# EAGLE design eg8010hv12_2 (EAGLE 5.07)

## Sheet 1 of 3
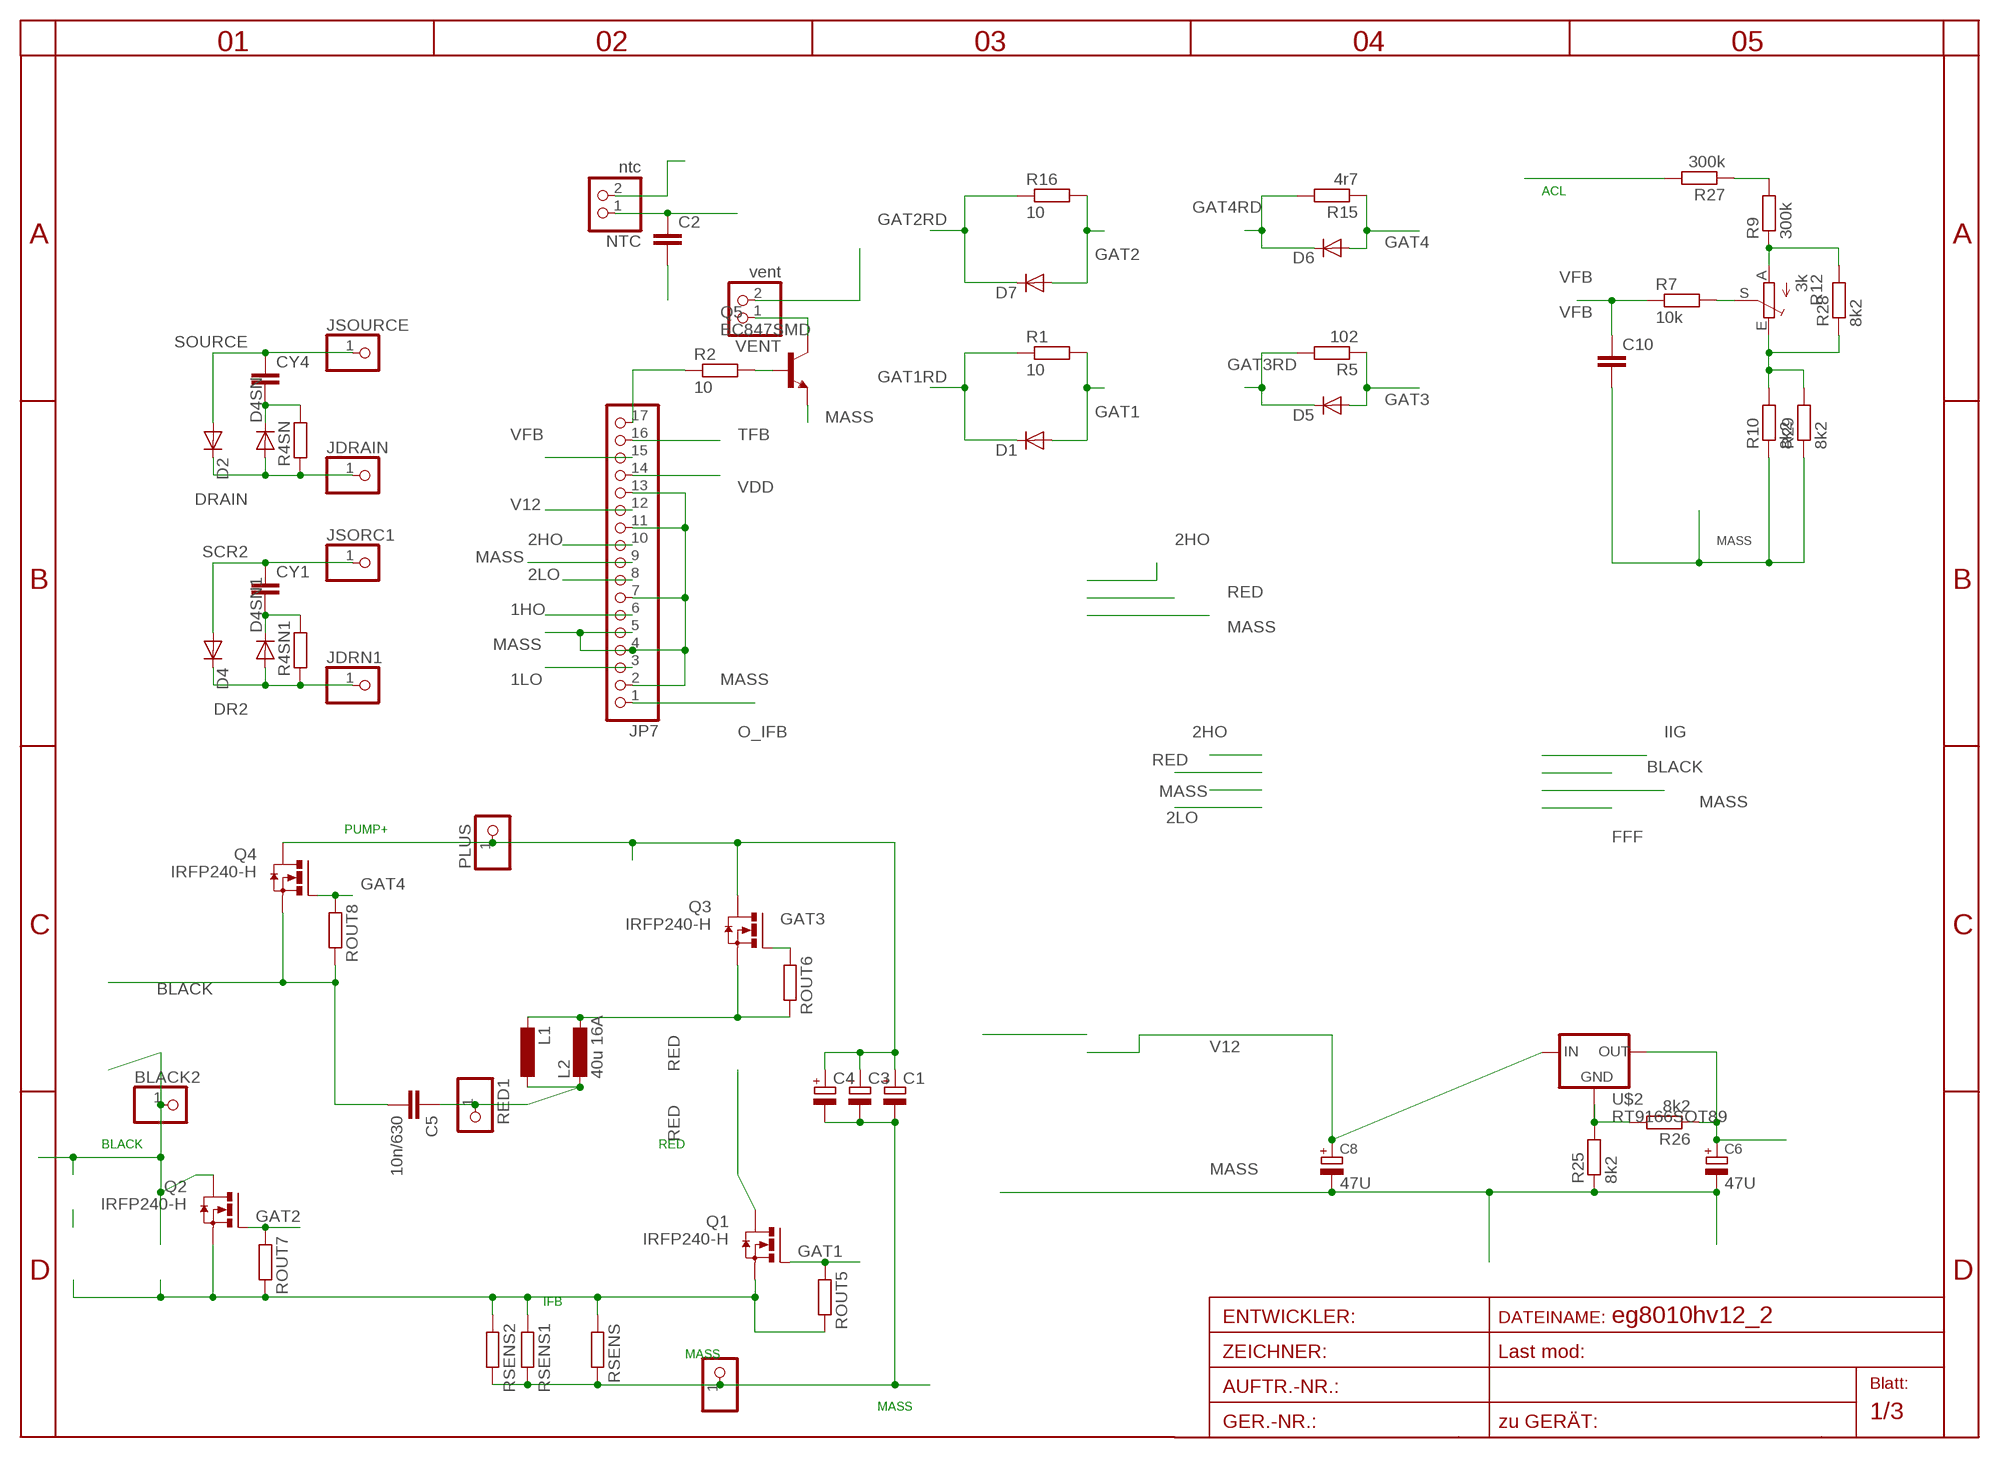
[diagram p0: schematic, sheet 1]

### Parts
BLACK2  PINHD-1X12MM3  [1X2MM3]
C1  CPOL-EUE5-13  [E5-13]
C2  C-EUC1206  [C1206]
C3  CPOL-EUE5-13  [E5-13]
C4  CPOL-EUE5-13  [E5-13]
C5  10n/630  C-EU275-173X316  [C275-173X316]
C6  47U  CPOL-EUSMCA  [SMC_A]
C8  47U  CPOL-EUSMCA  [SMC_A]
C10  C-EUC0805  [C0805]
CY1  CXXC10B5  [XC10B5]
CY4  CXXC10B5  [XC10B5]
D1  DIODE-SMA-DO214  [SMA-DO214AC]
D2  DIODE-SMC  [SMC]
D4  DIODE-SMC  [SMC]
D4SN  DIODE-P1-10  [P1-10]
D4SN1  DIODE-P1-10  [P1-10]
D5  DIODE-MINIMELF  [MINIMELF]
D6  DIODE-SMA-DO214  [SMA-DO214AC]
D7  DIODE-SMA-DO214  [SMA-DO214AC]
JDRAIN  PINHD-1X11MM0  [1X1MM0]
JDRN1  PINHD-1X11MM0  [1X1MM0]
JP7  PINHD-1X17  [1X17]
JSORC1  PINHD-1X11MM0  [1X1MM0]
JSOURCE  PINHD-1X11MM0  [1X1MM0]
L1  L-EU4.13  [0204/13]
L2  40u 16A  L-EURNG  [RING]
MINUS  PINHD-1X12MM3  [1X2MM3]
NTC  ntc  PINHD-1X2STR  [1X02]
PLUS  PINHD-1X12MM3  [1X2MM3]
Q1  IRFP240-H  [TO247BH]
Q2  IRFP240-H  [TO247BH]
Q3  IRFP240-H  [TO247BH]
Q4  IRFP240-H  [TO247BH]
Q5  BC847SMD  [SOT23]
R1  10  R-EU_R1206  [R1206]
R2  10  R-EU_R0805  [R0805]
R4SN  R-EU_0207/10  [0207/10]
R4SN1  R-EU_0207/10  [0207/10]
R5  102  R-EU_R1206  [R1206]
R7  10k  R-EU_R0805  [R0805]
R9  300k  R-EU_R1206  [R1206]
R10  8k2  R-EU_R0805  [R0805]
R12  3k  TRIM_EU-B64Y  [B64Y]
R15  4r7  R-EU_R1206  [R1206]
R16  10  R-EU_R1206  [R1206]
R25  8k2  R-EU_R0805  [R0805]
R26  8k2  R-EU_R0805  [R0805]
R27  300k  R-EU_R1206  [R1206]
R28  8k2  R-EU_R1206  [R1206]
R29  8k2  R-EU_R0805  [R0805]
RED1  PINHD-1X12MM3  [1X2MM3]
ROUT5  R-EU_R1206  [R1206]
ROUT6  R-EU_R1206  [R1206]
ROUT7  R-EU_R1206  [R1206]
ROUT8  R-EU_R1206  [R1206]
RSENS  R-EU_0204/7  [0204/7]
RSENS1  R-EU_0204/7  [0204/7]
RSENS2  R-EU_0922V  [0922V]
U$2  RT9166SOT89  [SOT89R]
VENT  vent  PINHD-1X2STR  [1X02]

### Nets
1HO: JP7.6 ; also sheet 3
1LO: JP7.3 ; also sheet 3
2HO: JP7.10 ; also sheet 3
2LO: JP7.8 ; also sheet 3
ACL: C5.1 L1.1 L2.2 R27.2 RED1.1
BLACK: BLACK2.1 C5.2 Q2.D Q4.S ROUT8.2 ; also sheet 3
DR2: D4.C D4SN1.A JDRN1.1 R4SN1.1
DRAIN: D2.C D4SN.A JDRAIN.1 R4SN.1
GAT1: D1.A Q1.G R1.2 ROUT5.1
GAT1RD: D1.K(C) R1.1 ; also sheet 3
GAT2: D7.A Q2.G R16.2 ROUT7.1
GAT2RD: D7.K(C) R16.1 ; also sheet 3
GAT3: D5.A Q3.G R5.1 ROUT6.1
GAT3RD: D5.C R5.2 ; also sheet 3
GAT4: D6.A Q4.G R15.1 ROUT8.1
GAT4RD: D6.K(C) R15.2 ; also sheet 3
IFB: Q1.S Q2.S ROUT5.2 ROUT7.2 RSENS1.1 RSENS2.1 RSENS.1 ; also sheet 3
MASS: C1.- C2.2 C3.- C4.- C6.- C8.- C10.2 JP7.2 JP7.4 JP7.5 JP7.7 JP7.9 JP7.11 JP7.13 MINUS.1 Q5.2(E) R10.1 R25.1 R29.1 RSENS1.2 RSENS2.2 RSENS.2 ; also sheet 2,3
N$1: Q5.3(C) VENT.1
N$2: Q5.1(B) R2.2
N$3: JP7.17 R2.1
N$17: R25.2 R26.2 U$2.3(GND) U$2.4(GND1)
N$23: R9.2 R27.1
N$29: R10.2 R12.E R28.1 R29.2
N$30: R9.1 R12.A R28.2
N$31: R7.2 R12.S
O_IFB: JP7.1 ; also sheet 3
PUMP+: C1.+ C3.+ C4.+ PLUS.1 Q3.D Q4.D ; also sheet 2
RED: L1.2 L2.1 Q1.D Q3.S ROUT6.2 ; also sheet 3
SCR2: CY1.1 D4.A JSORC1.1
SNUB1: CY1.2 D4SN1.C R4SN1.2
SNUB2: CY4.2 D4SN.C R4SN.2
SOURCE: CY4.1 D2.A JSOURCE.1
TFB: C2.1 JP7.16 NTC.1
V12: C8.+ JP7.12 U$2.1(IN) ; also sheet 2,3
VDD: C6.+ JP7.14 NTC.2 R26.1 U$2.2(OUT) VENT.2
VFB: C10.1 JP7.15 R7.1

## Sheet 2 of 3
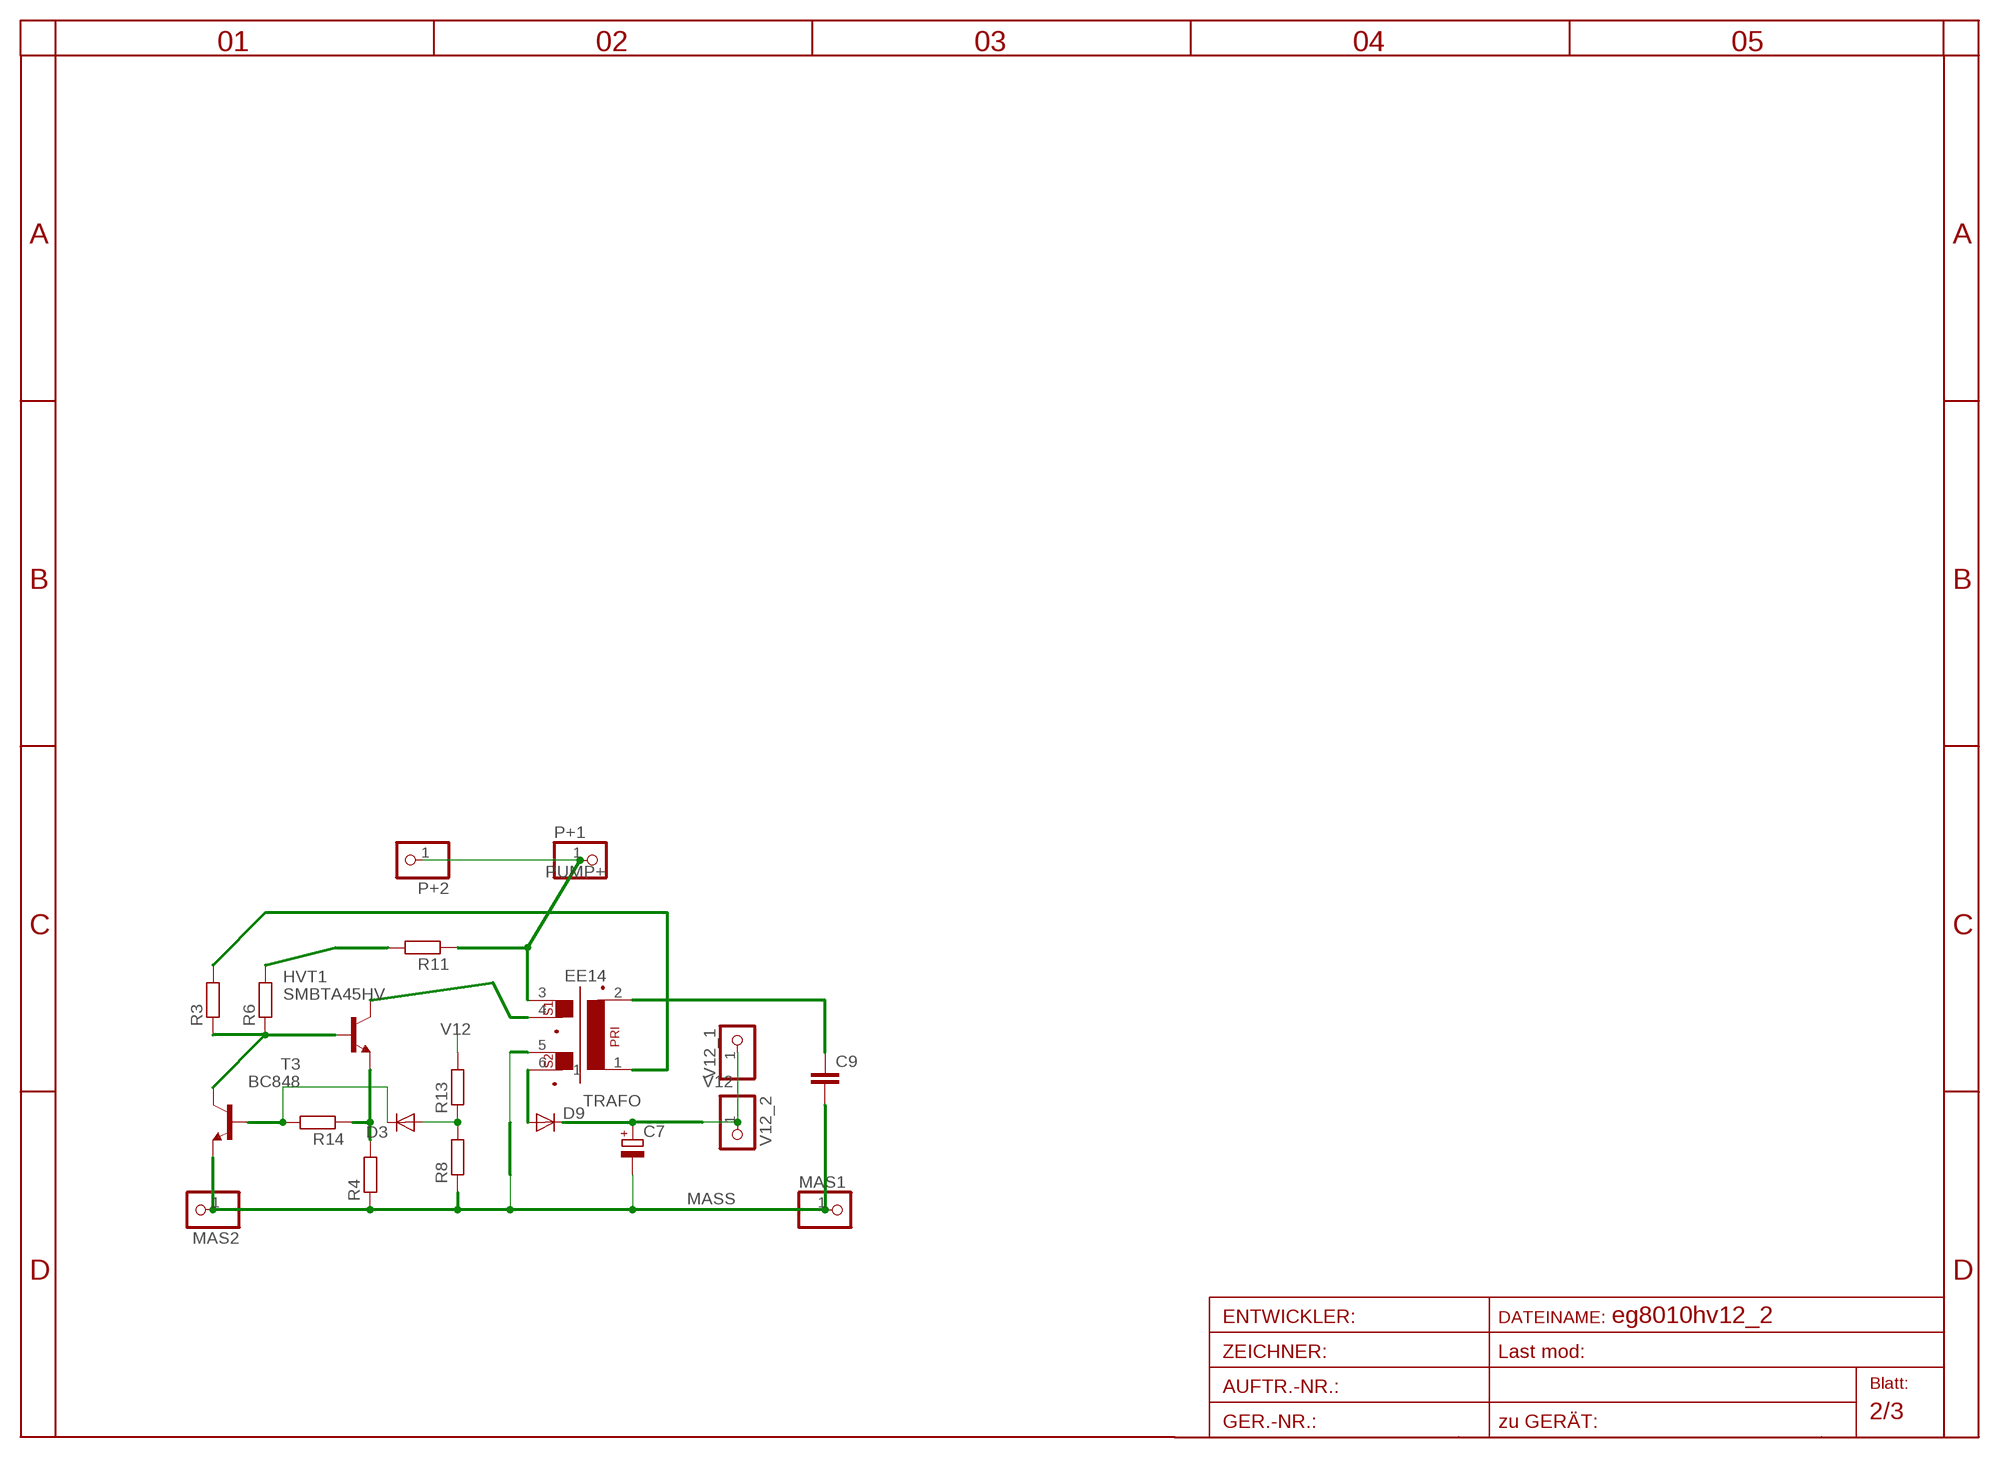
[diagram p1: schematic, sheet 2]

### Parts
C7  CPOL-EUSMCA  [SMC_A]
C9  C-EUC0805  [C0805]
D3  DIODE-MINIMELF  [MINIMELF]
D9  DIODE-SMA-DO214  [SMA-DO214AC]
HVT1  SMBTA45HV  [SOT23HV]
MAS1  PINHD-1X11X0.4  [1X01]
MAS2  PINHD-1X11X0.4  [1X01]
P+1  PINHD-1X11X0.4  [1X01]
P+2  PINHD-1X11X0.4  [1X01]
R3  R-EU_R0805  [R0805]
R4  R-EU_R0805  [R0805]
R6  R-EU_R1206  [R1206]
R8  R-EU_R0805  [R0805]
R11  R-EU_R1206  [R1206]
R13  R-EU_R0805  [R0805]
R14  R-EU_R0805  [R0805]
T3  BC848  [SOT23]
TRAFO  EE14  [EE14]
V12_1  PINHD-1X11X0.4  [1X01]
V12_2  PINHD-1X11X0.4  [1X01]

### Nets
A: D9.A TRAFO.6
B1C2: HVT1.1(B) R3.1 R6.1 T3.C
BT1: D3.C R14.2 T3.B
C1: HVT1.3(C) TRAFO.4
EB: HVT1.2(E) R4.2 R14.1
MASS: C7.- C9.2 MAS1.1 MAS2.1 R4.1 R8.1 T3.E TRAFO.5 ; also sheet 1,3
N$6: R3.2 TRAFO.1
N$7: C9.1 TRAFO.2
N$8: R6.2 R11.2
N$10: D3.A R8.2 R13.1
PUMP+: P+1.1 P+2.1 R11.1 TRAFO.3 ; also sheet 1
V12: C7.+ D9.K(C) R13.2 V12_1.1 V12_2.1 ; also sheet 1,3

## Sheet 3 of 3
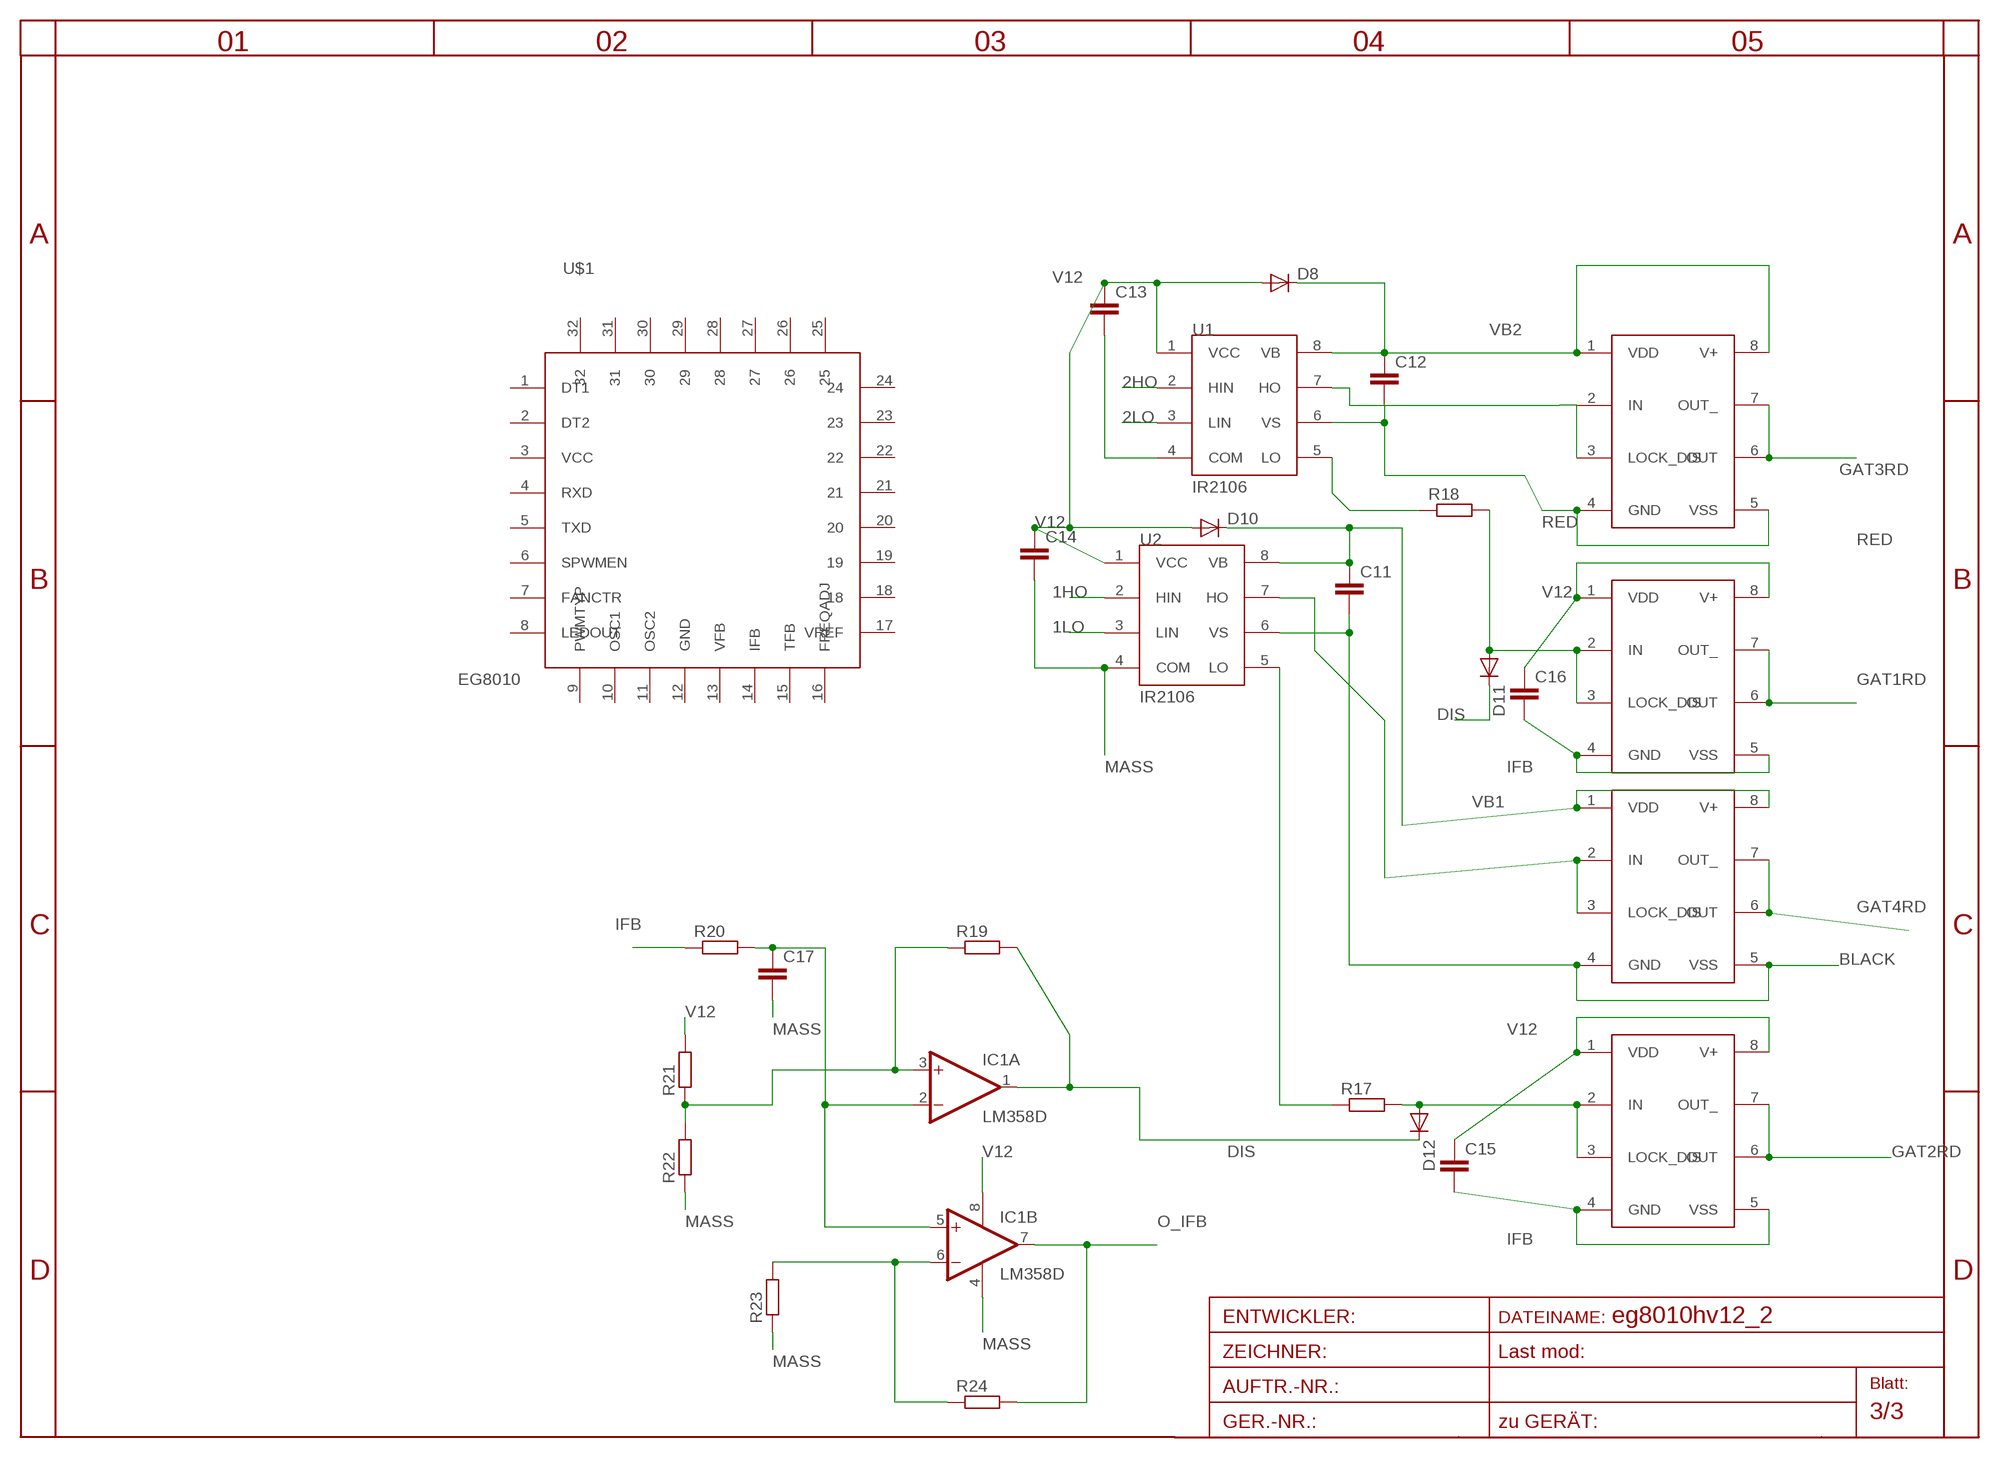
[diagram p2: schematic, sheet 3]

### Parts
1HDRV  TC4432X  [SO-08]
1LODRV  TC4432X  [SO-08]
2HDRV  TC4432X  [SO-08]
2LODRV  TC4432X  [SO-08]
C11  C-EUC1206  [C1206]
C12  C-EUC1206  [C1206]
C13  C-EUC1206  [C1206]
C14  C-EUC1206  [C1206]
C15  C-EUC1206  [C1206]
C16  C-EUC1206  [C1206]
C17  C-EUC1206  [C1206]
D8  DIODE-SMA-DO214  [SMA-DO214AC]
D10  DIODE-SMA-DO214  [SMA-DO214AC]
D11  DIODE-SOT23  [SOT23]
D12  DIODE-SOT23  [SOT23]
IC1  LM358D  [SO08]
R17  R-EU_0617/17  [0617/17]
R18  R-EU_0204/7  [0204/7]
R19  R-EU_R1206  [R1206]
R20  R-EU_R0805  [R0805]
R21  R-EU_R0805  [R0805]
R22  R-EU_R0805  [R0805]
R23  R-EU_R0805  [R0805]
R24  R-EU_R0805  [R0805]
U1  IR2106  [SO8-2]
U2  IR2106  [SO8-2]
U$1  EG8010  [EG8010-32]

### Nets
1HO: U2.2(HIN) ; also sheet 1
1LO: U2.3(LIN) ; also sheet 1
2HO: U1.2(HIN) ; also sheet 1
2LO: U1.3(LIN) ; also sheet 1
BLACK: 1HDRV.4(GND) 1HDRV.5(VSS) C11.2 U2.6(VS) ; also sheet 1
DIS: D11.3(C) D12.3(C) IC1.1(A:OUT) R19.2
GAT1RD: 2LODRV.6(OUT) 2LODRV.7(OUT_) ; also sheet 1
GAT2RD: 1LODRV.6(OUT) 1LODRV.7(OUT_) ; also sheet 1
GAT3RD: 2HDRV.6(OUT) 2HDRV.7(OUT_) ; also sheet 1
GAT4RD: 1HDRV.6(OUT) 1HDRV.7(OUT_) ; also sheet 1
IFB: 1LODRV.4(GND) 1LODRV.5(VSS) 2LODRV.4(GND) 2LODRV.5(VSS) C15.2 C16.2 R20.1 ; also sheet 1
MASS: C13.2 C14.2 C17.2 IC1.4(P:V-) R22.1 R23.1 U1.4(COM) U2.4(COM) ; also sheet 1,2
N$4: R18.1 U1.5(LO)
N$5: 1LODRV.2(IN) 1LODRV.3(LOCK_DIS) D12.1(A) R17.2
N$9: IC1.3(A:+IN) R19.1 R21.1 R22.2
N$11: R17.1 U2.5(LO)
N$12: 2HDRV.2(IN) 2HDRV.3(LOCK_DIS) U1.7(HO)
N$13: 1HDRV.2(IN) 1HDRV.3(LOCK_DIS) U2.7(HO)
N$15: C17.1 IC1.2(A:-IN) IC1.5(B:+IN) R20.2
N$16: 2LODRV.2(IN) 2LODRV.3(LOCK_DIS) D11.1(A) R18.2
N$18: IC1.6(B:-IN) R23.2 R24.1
O_IFB: IC1.7(B:OUT) R24.2 ; also sheet 1
RED: 2HDRV.4(GND) 2HDRV.5(VSS) C12.2 U1.6(VS) ; also sheet 1
V12: 1LODRV.1(VDD) 1LODRV.8(V+) 2LODRV.1(VDD) 2LODRV.8(V+) C13.1 C14.1 C15.1 C16.1 D8.A D10.A IC1.8(P:V+) R21.2 U1.1(VCC) U2.1(VCC) ; also sheet 1,2
VB1: 1HDRV.1(VDD) 1HDRV.8(V+) C11.1 D10.K(C) U2.8(VB)
VB2: 2HDRV.1(VDD) 2HDRV.8(V+) C12.1 D8.K(C) U1.8(VB)
Unconnected: U$1.1(DT1) U$1.2(DT2) U$1.4(RXD) U$1.5(TXD) U$1.6(SPWMEN) U$1.8(LEDOUT) U$1.9(PWMTYP) U$1.10(OSC1) U$1.11(OSC2) U$1.12(GND) U$1.13(VFB) U$1.14(IFB) U$1.15(TFB) U$1.16(FREQADJ) U$1.17(VREF) U$1.18 U$1.19 U$1.20 U$1.21 U$1.22 U$1.23 U$1.24 U$1.26 U$1.27 U$1.29 U$1.30 U$1.31 U$1.32

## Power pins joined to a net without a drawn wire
25: U$1.25
28: U$1.28
FANCTR: U$1.7(FANCTR)
VCC: U$1.3(VCC)

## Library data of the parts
1HDRV 1LODRV 2HDRV 2LODRV = microchip:TC4432
BLACK2 JDRAIN JDRN1 JSORC1 JSOURCE MAS1 MAS2 MINUS P+1 P+2 PLUS RED1 V12_1 V12_2 = pinhead:PINHD-1X1: PIN HEADER
C1 C3 C4 C6-C8 = rcl:CPOL-EU: POLARIZED CAPACITOR, European symbol
C2 C5 C9-C17 = rcl:C-EU: CAPACITOR, European symbol
CY1 CY4 = rcl:CX: X CAPACITOR
D1-D4 D4SN D4SN1 D5-D12 = diode:DIODE-: DIODE
HVT1 = transistor-npn:SMBTA45
IC1 = linear:LM358: OP AMP also LM158; LM258; LM2904 Source: http://cache.national.com/ds/LM/LM158.pdf
JP7 = pinhead:PINHD-1X17: PIN HEADER
L1 L2 = rcl:L-EU: INDUCTOR, European symbol
NTC VENT = pinhead:PINHD-1X2: PIN HEADER
Q1-Q4 = transistor-power:IRFP240: HEXFET Power MosFet Source: http://www.irf.com/
Q5 = transistor-npn:BC847*: NPN Transistor
R1-R4 R4SN R4SN1 R5 R6 R8 R11 R13-R16 R18-R24 ROUT5-ROUT8 RSENS RSENS1 RSENS2 = rcl:R-EU_: RESISTOR, European symbol
R7 R9 R10 R17 R25-R29 = rcl-2:R-EU_: RESISTOR, European symbol
R12 = pot:TRIM_EU-: POTENTIOMETER
T3 = transistor:BC848: NPN TRANSISTOR
TRAFO = trafo:EE14
U1 U2 = irf-2:IR2106
U$1 = texas:EG8010
U$2 = v-reg:RT9166

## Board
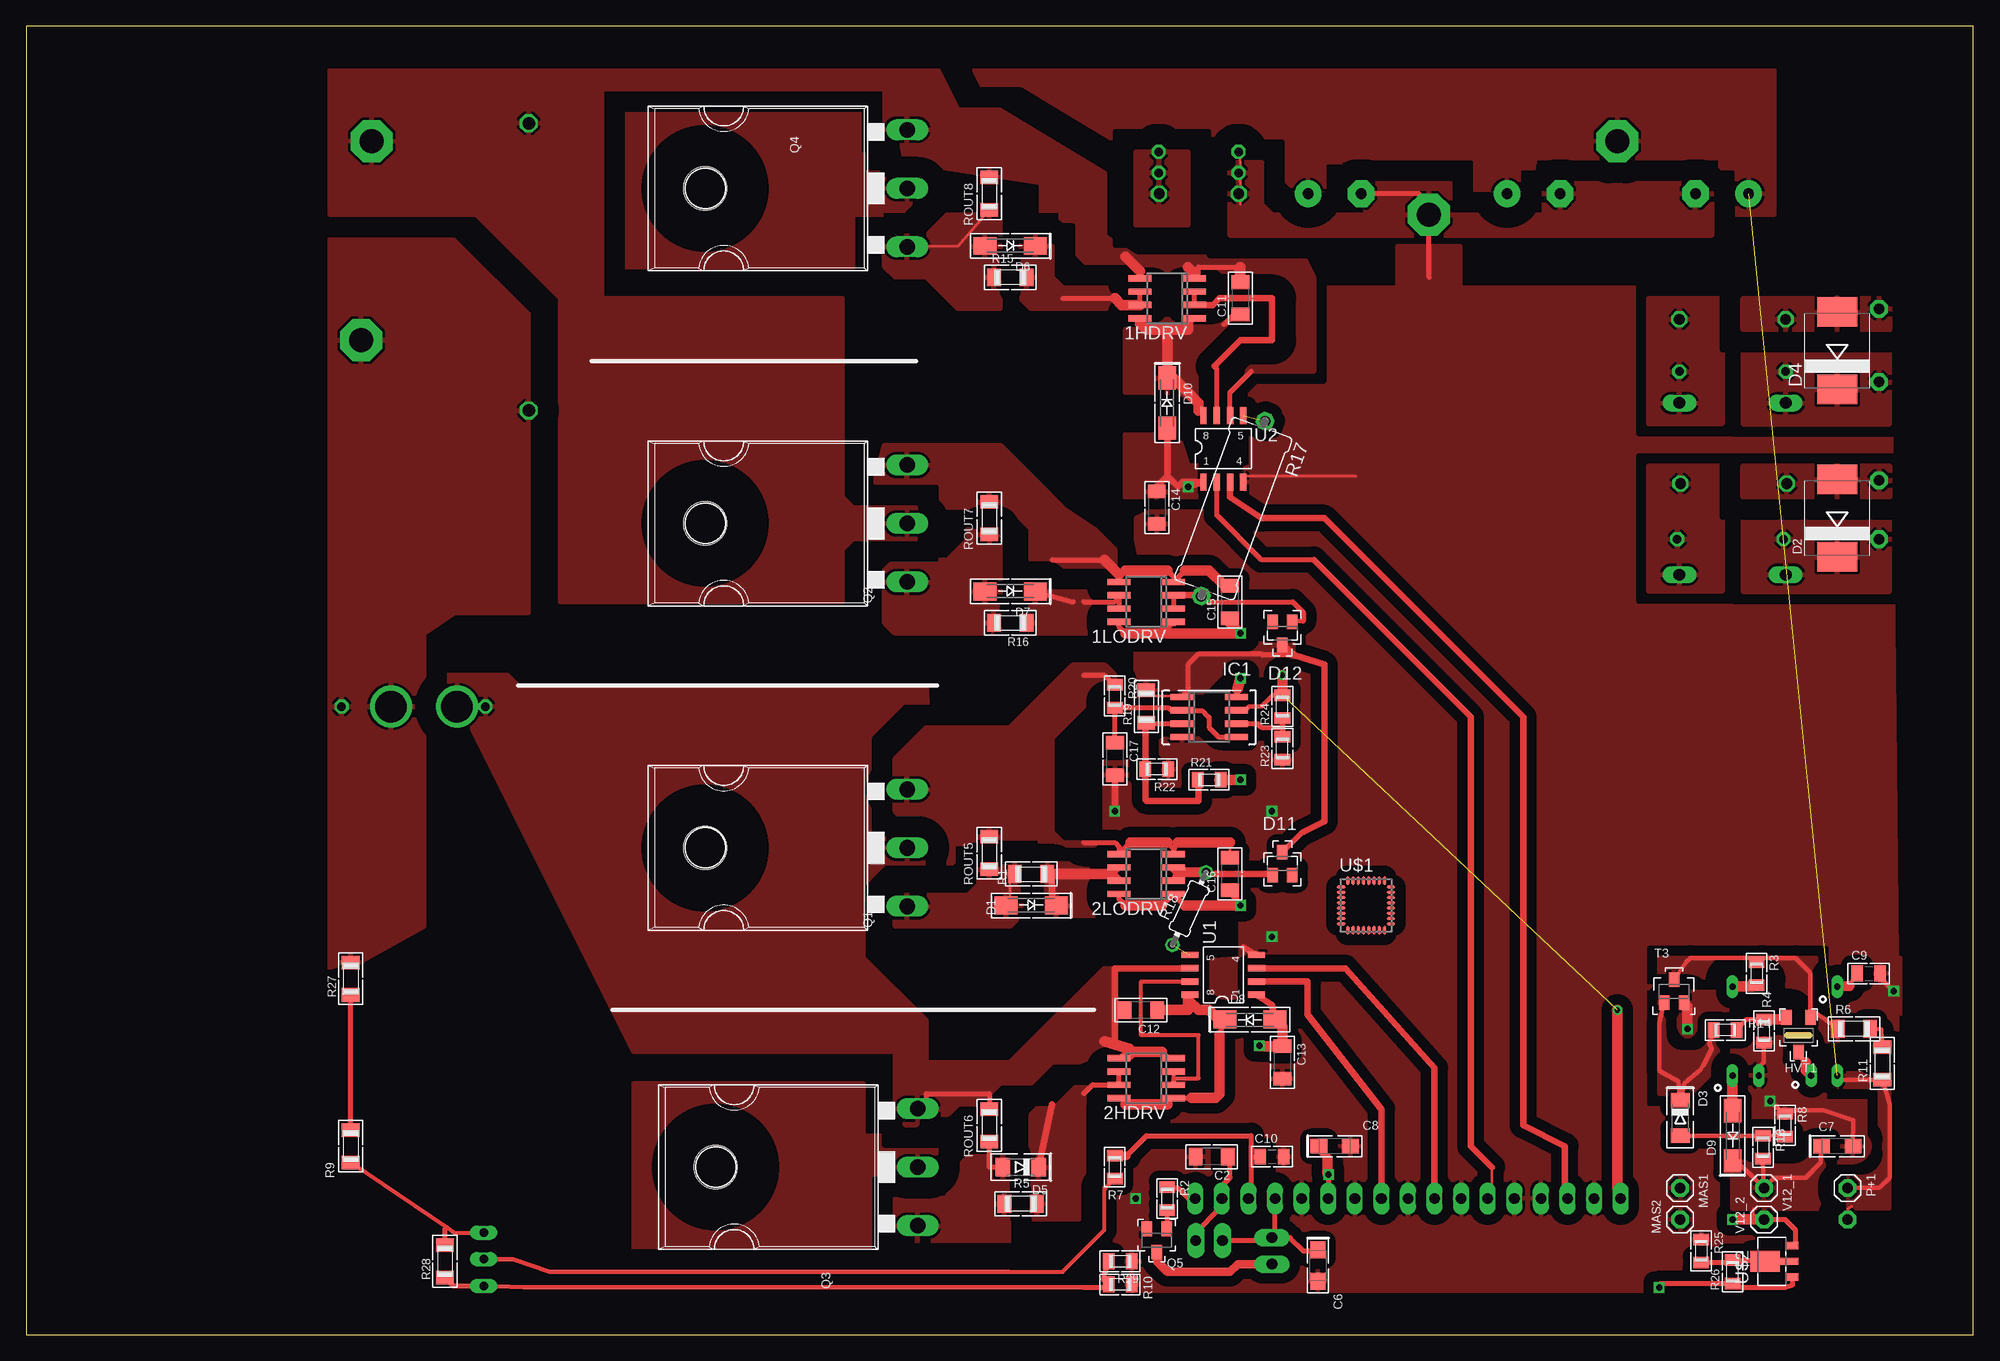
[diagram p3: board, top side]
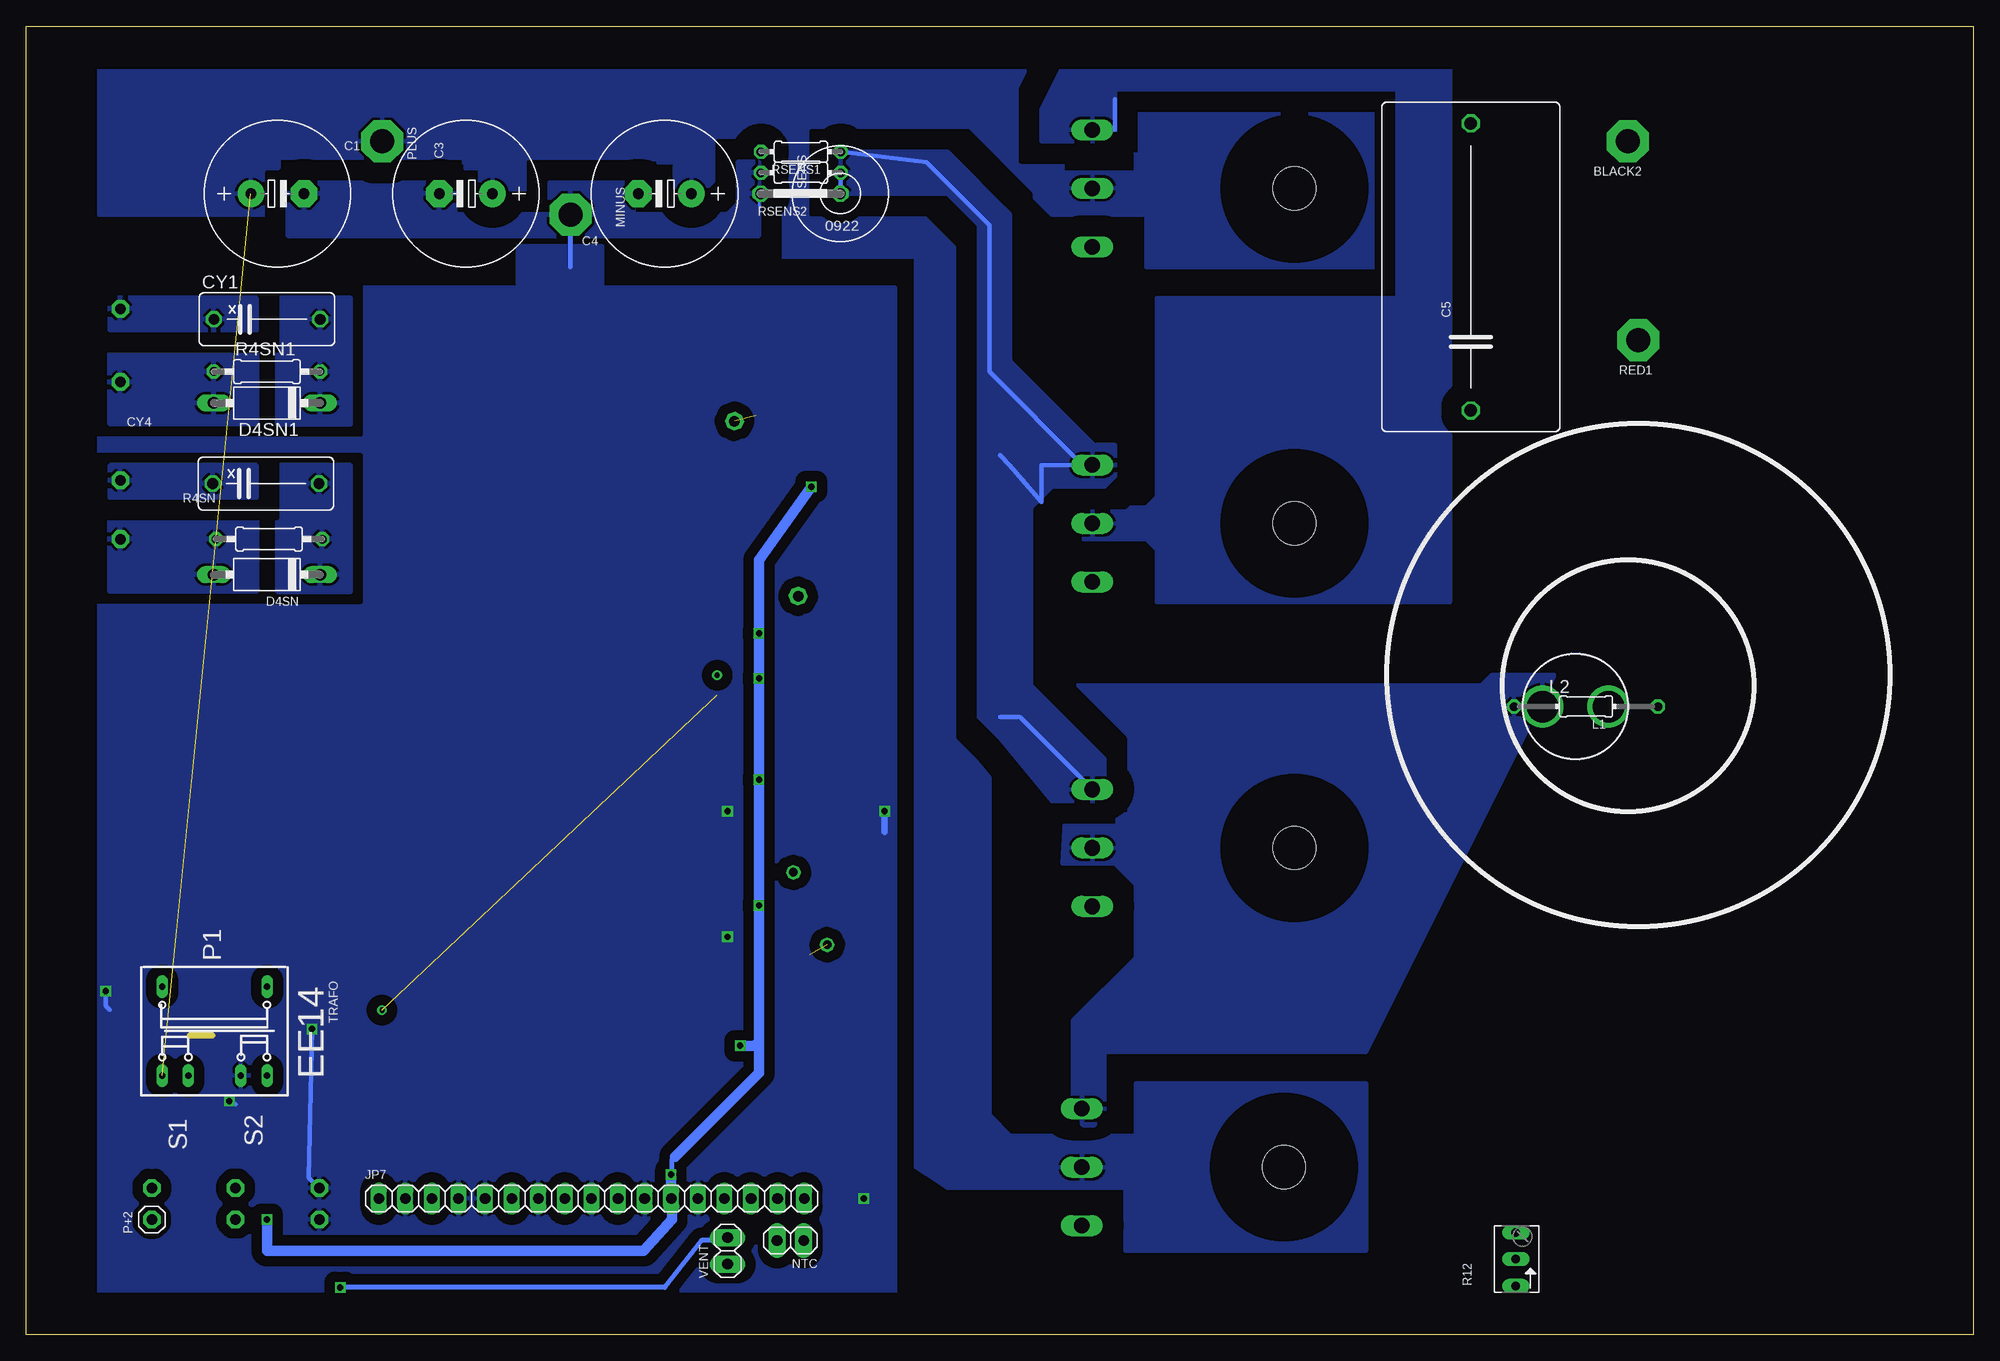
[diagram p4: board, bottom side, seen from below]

Size 186 x 125 mm. Coordinates in mm from the lower left corner, seen from the top.
Outline: 0,0 186,0 186,125 0,125 0,0
Copper layers (1*16): Top 0.035mm / dielectric 1.5mm / Bottom 0.035mm
Design rules "default *": minimum track width 10mil, minimum drill 20mil, track to track 8mil, track to pad 8mil, pad to pad 8mil, via to via 8mil, smd to smd 8mil, copper to edge 4mm, drill to drill 8mil, minimum pad ring 10mil, minimum via ring 8mil, stop-mask expansion 4mil, vias tented up to drill 0mil, thermal gap 10mil

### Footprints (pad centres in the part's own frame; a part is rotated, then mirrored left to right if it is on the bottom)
SO-08 = smd 0.6 x 2.2: 1 -1.905,-2.6; 2 -0.635,-2.6; 3 0.635,-2.6; 4 1.905,-2.6; 5 1.905,2.6; 6 0.635,2.6; 7 -0.635,2.6; 8 -1.905,2.6
1X2MM3 = drill 2.3 pad 4 octagon: 1 0,0
E5-13 = drill 1.016 pad 2.54 round: + -2.54,0 | drill 1.016 pad 2.54 octagon: - 2.54,0
C1206 = smd 1.3 x 1.7: 1 -1.55,0; 2 1.55,0
C275-173X316 = drill 1.194 octagon: 1 -13.716,0; 2 13.716,0
SMC_A = smd 1.6 x 1.4: + -1.5,0; - 1.5,0
C0805 = smd 1.1 x 1.5: 1 -1.1,0; 2 1.1,0
XC10B5 = drill 1.016 octagon: 1 -5.08,0; 2 5.08,0
SMA-DO214AC = smd 2.2 x 1.7: A 2.4,0; K -2.4,0
SMC = smd 2.8 x 3.8: A 3.7,0; C -3.7,0
MINIMELF = smd 1.4 x 1.8: A 1.7,0; C -1.7,0
P1-10 = drill 1.118 long: A 5.08,0; C -5.08,0
SOT23 = smd 1 x 1.4: 1 -0.95,-1.1; 2 0.95,-1.1; 3 0,1.1
SOT23HV = smd 1 x 1.4: 1 -1.15,-1.7; 2 1.15,-1.7; 3 0,1.6
SO08 = smd 0.6 x 2.2: 1 -1.905,-2.6; 2 -0.635,-2.6; 3 0.635,-2.6; 4 1.905,-2.6; 5 1.905,2.6; 6 0.635,2.6; 7 -0.635,2.6; 8 -1.905,2.6
1X1MM0 = drill 1 pad 1.676 octagon: 1 0,0
1X17 = drill 1.016 long: 1 -20.32,0; 2 -17.78,0; 3 -15.24,0; 4 -12.7,0; 5 -10.16,0; 6 -7.62,0; 7 -5.08,0; 8 -2.54,0; 9 0,0; 10 2.54,0; 11 5.08,0; 12 7.62,0; 13 10.16,0; 14 12.7,0; 15 15.24,0; 16 17.78,0; 17 20.32,0
0204/13 = drill 0.813 octagon: 1 -6.872,0; 2 6.872,0
RING = drill 3 pad 4 round: 1 -3.15,0; 2 3.15,0
1X01 = drill 1 pad 1.676 octagon: 1 0,0
1X02 = drill 1.016 pad 1.676 long: 1 -1.27,0; 2 1.27,0
TO247BH = drill 1.499 long: D 0,-10.16; G -5.588,-10.16; S 5.588,-10.16 | hole 4.115: 0,9.144
R1206 = smd 1.3 x 1.7: 1 -1.55,0; 2 1.55,0
R0805 = smd 1.1 x 1.5: 1 -1.1,0; 2 1.1,0
0207/10 = drill 0.813 octagon: 1 -5.08,0; 2 5.08,0
B64Y = drill 0.813 long: A 2.54,0; E -2.54,0; S 0,0
0617/17 = drill 1 pad 1.676 octagon: 1 -8.89,0; 2 8.89,0
0204/7 = drill 0.813 octagon: 1 -3.81,0; 2 3.81,0
0922V = drill 1.016 octagon: 1 -5.08,0; 2 2.54,0
SOT23' = smd 1 x 1.4: B -0.95,-1.1; C 0,1.1; E 0.95,-1.1
EE14 = drill 0.6 pad 1 long: 1 4.25,-5; 2 4.25,5; 3 -4.25,5 | drill 0.6 pad 1.016 long: 4 -4.25,2.5; 5 -4.25,-2.5; 6 -4.25,-5
SO8-2 = smd 0.61 x 1.626: 1 -2.54,-2.54; 2 -1.27,-2.54; 3 0,-2.54; 4 1.27,-2.54; 5 1.27,3.81; 6 0,3.81; 7 -1.27,3.81; 8 -2.54,3.81
EG8010-32 = smd 0.85 x 0.3: 1 -2.375,1.75; 2 -2.375,1.25; 3 -2.375,0.75; 4 -2.375,0.25; 5 -2.375,-0.25; 6 -2.375,-0.75; 7 -2.375,-1.25; 8 -2.375,-1.75; 17 2.375,-1.75; 18 2.375,-1.25; 19 2.375,-0.75; 20 2.375,-0.25; 21 2.375,0.25; 22 2.375,0.75; 23 2.375,1.25; 24 2.375,1.75 | smd 0.3 x 0.85: 9 -1.75,-2.375; 10 -1.25,-2.375; 11 -0.75,-2.375; 12 -0.25,-2.375; 13 0.25,-2.375; 14 0.75,-2.375; 15 1.25,-2.375; 16 1.75,-2.375; 25 1.75,2.375; 26 1.25,2.375; 27 0.75,2.375; 28 0.25,2.375; 29 -0.25,2.375; 30 -0.75,2.375; 31 -1.25,2.375; 32 -1.75,2.375
SOT89R = smd 0.7 x 1.1: 1 1.5,-1.75; 2 -1.5,-1.75 | smd 0.7 x 1.8: 3 0,-1.4 | smd 2 x 2.8: 4 0,0.9

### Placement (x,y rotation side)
1HDRV  109,99 90 top
1LODRV  107,70 90 top
2HDRV  107,24.5 90 top
2LODRV  107,44 90 top
BLACK2  33,114 180 bottom
C1  162,109 0 bottom
C2  113.25,17 180 top
C3  144,109 180 bottom
C4  125,109 180 bottom
C5  48,102 90 bottom
C6  123.4,6.6 270 top
C7  173,18 0 top
C8  125,18 0 top
C9  176,34.5 0 top
C10  119,17 0 top
C11  116,99 90 top
C12  106.5,31 180 top
C13  120,26 270 top
C14  108,79 270 top
C15  115,70 90 top
C16  115,44 90 top
C17  104,55 270 top
CY1  163,97 0 bottom
CY4  163.1,81.3 0 bottom
D1  96,41 180 top
D2  173,78 90 top
D3  158,20.7 270 top
D4  173,94 90 top
D4SN  163,72.6 180 bottom
D4SN1  163,89 180 bottom
D5  95,16 180 top
D6  94,104 180 top
D7  94,71 180 top
D8  116.9,30.1 0 top
D9  163,19 90 top
D10  109,89 270 top
D11  120,45 0 top
D12  120,67 180 top
HVT1  169.3,28.6 180 top
IC1  113,59 270 top
JDRAIN  177,76 270 top
JDRN1  177,91 0 top
JP7  132,13 0 bottom
JSORC1  177,98 0 top
JSOURCE  177,81.6 270 top
L1  37,60 180 bottom
L2  38,60 0 bottom
MAS1  158,14 270 top
MAS2  158,11 90 top
MINUS  134,107 270 bottom
NTC  113,9 180 bottom
P+1  174,14 270 top
P+2  174,11 90 bottom
PLUS  152,114 270 bottom
Q1  74,46.5 90 top
Q2  74,77.5 90 top
Q3  75,16 90 top
Q4  74,109.5 90 top
Q5  108,9 180 top
R1  96,44 180 top
R2  109,13 270 top
R3  165.3,34.5 270 top
R4  166,29 90 top
R4SN  162.8,76 0 bottom
R4SN1  163,92 0 bottom
R5  95,12.5 0 top
R6  174.6,29.2 0 top
R7  104,16 270 top
R8  168,20 270 top
R9  31,18 90 top
R10  104.5,4.8 180 top
R11  177.3,25.9 90 top
R12  43.7,7.2 90 bottom
R13  165.9,17.9 270 top
R14  162.3,29.1 180 top
R15  94,101 0 top
R16  94,68 180 top
R17  115.3,78.9 250 top
R18  111.1,40.7 65 top
R19  107,60 90 top
R20  104,61 270 top
R21  113,53 0 top
R22  108,54 180 top
R23  120,56 90 top
R24  120,60 90 top
R25  160,8 270 top
R26  163,6 90 top
R27  31,34 90 top
R28  40,7 90 top
R29  104.5,7 180 top
RED1  32,95 180 bottom
ROUT5  92,46 90 top
ROUT6  92,20 90 top
ROUT7  92,78 90 top
ROUT8  92,109 90 top
RSENS  112,111 180 bottom
RSENS1  112,113 180 bottom
RSENS2  113.3,109 180 bottom
T3  BC848  [SOT23']  157.4,32.8 0 top
TRAFO  168,29 90 bottom
U1  115,35 90 top
U2  115,84 0 top
U$1  128,41 0 top
U$2  167,7 90 top
V12_1  166,14 270 top
V12_2  166,11 90 top
VENT  119,8 90 bottom

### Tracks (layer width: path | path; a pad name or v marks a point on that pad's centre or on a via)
1HO
  Top 0.254: 140,16 140,14 JP7.6
  Top 0.5: U2.2 113.73,78.27 118,74 123,74
  Top 0.6: 140,16 138,18 138,59 123,74
1LO
  Top 0.6: JP7.3 147,13.76 147,18 143,20 143,59 124,78 118,78 115,80 U2.3
2HO
  Top 0.6: U1.2 122.41,33.73 122.4,30.6 129.46,21.54 JP7.10
2LO
  Top 0.6: U1.3 126,35 134.54,25.46 JP7.8
A
  Top 1: D9.A TRAFO.6
ACL
  pour Top (isolate 2, rank 2): 30,122 29,121 29,34 38,39 38,67 41,69 48,69 48,121
B1C2
  Top 0.406: R6.1 171.05,30.7 HVT1.1 170.45,34.55 169,36 165.9,36 | 165.7,36 R3.1 165.9,36 | T3.C 158.6,35.6 159,36 165.7,36 | 165.7,36 165.9,36
  pour Top (isolate 2): 171,31 171,36 156,36 156,33 169,33 169,31 172,28 174,28 174,30
BLACK
  Top 0.5: 1HDRV.5 106.4,101.6 | 111.6,101.4 1HDRV.4 111.91,100.91 112,101 112,102 116,102 115.64,101.64 115.64,100.91 | U2.6 115,90 117,92
  Top 0.6: C11.2 115.64,100.91
  Top 1: 106.4,101.6 105,103 | 111.6,101.4 111,102 | 116,102 C11.2
  Bottom 0.406: Q4.S 82,115.09 82,118
  pour Bottom (isolate 2, rank 2): 89,117 89,114 82,114 82,119 55,119 55,99 78,99 78,80 79,79 85,79 85,76 79,76 78,75 78,70 50,70 50,121 87,121
  pour Top (isolate 2, rank 3): 83,117 93,117 103,111 103,105 106,103 122,103 123,101 123,92 116,92 121,99 120,100 103,100 97,106 97,110 84,112
  pour Top (isolate 2): 89,117 89,114 82,114 82,119 55,119 55,99 78,99 78,80 79,79 85,79 85,76 79,76 78,75 78,70 51,70 51,99 43,107 29,107 29,121 87,121
BT1
  Top 0.406: T3.B 156,29.75 156,25.2 157.8,24.2 D3.C 158.4,24 159.9,25.3 160.2,25.7 161,27.3 160.8,27.8 R14.2
  pour Top (isolate 1.5, rank 2): 163,29 163,27 159,23 156,23 156,32 158,32 158,31 160,29
C1
  Top 0.406: HVT1.3 169.3,26.7 170,26
  Top 1: 170,26 170,25.25 TRAFO.4
DIS
  Top 0.254: R19.2 107,61 110,61 IC1.1
  Top 0.5: 122,48 121.9,48 D11.3 | 121.1,64.9 118.1,64.9 118,65 112,65 111,64 111,61.51 IC1.1
  Top 0.6: 122,48 124,49 124,64 121.1,64.9 D12.3
  pour Top (isolate 1.27, rank 2): 106,67 121,67 121,63 114,63 112,61 106,61 106,66
DR2
  pour Top (isolate 2, rank 2): 178,94 164,94 164,87 178,87
  pour Bottom (isolate 2, rank 2): 178,94 164,94 164,87 178,87
DRAIN
  pour Top (isolate 2, rank 2): 178,78 164,78 164,71 178,71
  pour Bottom (isolate 2, rank 2): 178,78 164,78 164,71 178,71
EB
  Top 0.406: R14.1 164.3,30.1 R4.2 | 167.95,30.1 HVT1.2
  Top 1: R4.2 167.95,30.1
GAT1
  Top 0.254: R1.2 94,44 94,41 D1.A
  pour Top (isolate 2): 83,42 90,42 91,43 91,45 95,45 95,40 94,39 83,39
GAT1RD
  Top 0.5: 2LODRV.7 104.4,43.6 103.88,44.12
  Top 0.6: 103.77,44 103.88,44.12 2LODRV.6 | R1.1 98,44 98,41.4 D1.K
  Top 1: 98,44 103.77,44
  pour Top (isolate 2, rank 2): 97,45 104,45 103,44 103,40 98,40
GAT2
  pour Top (isolate 2, rank 2): 82,73 83,74 88,74 90,76 90,77 92,77 93,76 93,68 92,67 83,67 82,68 82,70
GAT2RD
  Top 0.5: 1LODRV.7 1LODRV.6 104.4,70.4 104,70 101,70 | D7.K 100,70
  pour Top (isolate 2): 96,71 105,71 105,68 104,67 96,67
GAT3
  Top 0.5: D5.A 92,16 ROUT6.1
  pour Top (isolate 2, rank 3): 83,13 83,9 94,9 94,17 90,17 88,15 88,13 84,13
GAT3RD
  Top 0.5: 101,23 101.86,23.86 2HDRV.7 2HDRV.6
  Top 0.6: D5.C 98,22
  pour Top (isolate 2, rank 2): 103,25 106,25 106,23 102,23 101,22 101,11 96,11 96,21 99,24 100,24 101,25
GAT4
  Top 0.254: Q4.G 85,104 89,104 ROUT8.1
  pour Top (isolate 2, rank 2): 82,105 86,105 88,107 93,107 93,98 89,98 86,101 83,101 82,102
GAT4RD
  Top 0.5: 1HDRV.7 1HDRV.6 | 99,99 104,99
  Top 1: 1HDRV.7 104.64,98.36 104,99
  pour Top (isolate 2, rank 2): 107,98 96,98 95,99 95,104 96,105 97,105 98,104 98,101 99,100 107,100
IFB
  Top 0.254: 115,47 C16.2 | 2LODRV.4 110,47
  Top 0.5: 2LODRV.4 109.6,46.4 109,47 | 105.5,47 2LODRV.5 104.4,46.6 104,47 101,47 | 105,73 104.4,72.4 1LODRV.5 104.4,72.6 | 109,73 110,72 109.69,72 1LODRV.4 110.69,73 | 114.45,71.55 C15.2 | 98,74 103,74 | R20.1 103.9,62.1 103,63 101,63
  Top 1: 110,47 115,47 | 105.5,47 109,47 | 105,73 109,73 | 114.45,71.55 113,73 110.69,73 | 103,74 104.4,72.6
  Bottom 0.406: RSENS.1 108.19,109.59 | Q1.S 91.07,59 93,59 | 93,84 92.08,83.08 89,79.55 88.99,83.09 Q2.S 85.09,83.09 94,92 94,106 100,112 RSENS1.1
  pour Bottom (isolate 2): 109,113 109,109 98,109 95,106 95,59 93,57 88,51 84,51 83,52 83,55 90,62 90,79 88,81 83,81 82,82 82,85 84,85 92,93 92,107 98,113
  pour Top (isolate 2, rank 2): 106,113 111,113 111,106 106,106
  pour Top (isolate 2, rank 2): 83,54 83,55 86,58 94,58 100,64 103,64 104,63 104,61 102,61 98,57 98,48 99,47 105,47 105,45 88,45 83,50
  pour Top (isolate 2, rank 2): 82,85 93,85 99,79 102,77 104,75 104,71 99,71 96,74 96,77 94,79 83,79 81,81
MASS  (via drill 0.6)
  Top 0.254: 116,110 116,112 RSENS1.2 | 127,82 116,82 U2.4 | C4.- 127,109 | 116,110 116,108 RSENS2.2 | 116,110 RSENS.2
  Top 0.406: C7.- 174.55,20.45 171.7,21.4 168.8,21.4 R8.1 167.9,21.1 v166.6,22.3 | C9.2 177.1,34.1 v178.4,32.8 | TRAFO.5 165.5,25.5 166,26 R4.1
  Top 0.5: C4.- 133,109 134,108 134,101
  Top 0.6: 116.27,37 U1.4 | v104,50 C17.2
  Top 1: v158.7,29.2 158.7,31.35 T3.E
  Bottom 0.254: RSENS2.2 116,108 115.89,107.73
  Bottom 0.406: v158.7,29.2 159,15 MAS1.1 | v178.4,32.8 178.4,31.4 178,31 | v166.6,22.3 166,22
  Bottom 0.5: 134,102 MINUS.1
  Bottom 0.6: 104,48 v104,50
  other vias: 119,38 106,13 119,50
  pour Bottom (isolate 2): 179,36 179,12 156,12 156,36
  pour Top (isolate 2, rank 5): 179,36 179,12 156,12 156,36
  pour Bottom (isolate 1, rank 4): 103,100 131,100 131,104 139,104 139,100 179,100 179,4 103,4
  pour Top (isolate 1, rank 4): 103,100 131,100 131,104 137,104 137,100 178,100 179,4 103,4 103,35 116,36 116,40 103,40 103,62 107,71 106,76 106,78 117,83 117,86 103,86
  pour Bottom (isolate 2, rank 2): 116,112 118,112 118,108 119,107 128,107 128,110 136,110 136,107 145,107 145,110 160,110 161,109 161,105 116,105
  pour Top (isolate 2, rank 2): 115,112 118,112 118,108 119,107 128,107 128,110 136,110 136,107 145,107 145,110 160,110 161,109 161,105 115,105
N$1
  Top 0.8: VENT.1 115.73,6.73 115,6 109,6 108,7 108,8 108.1,7 Q5.3
N$2
  Top 0.5: R2.2 109,10.15 Q5.1
N$3
  Top 0.5: JP7.17 111,13 110,14 109.1,14 R2.1
N$4  (1 unrouted)
N$5
  Top 0.5: 113,70 121,70 122,69 122,68.15 D12.1 | 1LODRV.3 1LODRV.2
  Top 0.6: 113,70 112.73,70.27 R17.2 111.59,70.64 1LODRV.3
N$6
  Top 0.406: 164.95,33.25 R3.2
  Top 1: TRAFO.1 164.95,33.25
N$7
  Top 0.406: 174.15,33.3 C9.1
  Top 1: TRAFO.2 174.15,33.3
N$8
  Top 0.406: R11.2 177.2,29.15 R6.2
N$9
  Top 0.5: IC1.3 107.08,58.37 R19.1
  Top 0.6: R21.1 112,52.9 112,51 107,51 106.9,51.1 R22.2 106.9,58.35 R19.1
N$10
  Top 0.406: R8.2 167.8,19.1 R13.1 D3.A
N$11  (1 unrouted)
N$12
  Top 0.4: U1.7 106.5,33.73 106.5,28.6 112,28.6 112,24.5 109.6,24.5 2HDRV.3
  Top 0.5: 109.6,24.5 2HDRV.2
N$13
  Top 0.5: 1HDRV.2 1HDRV.3 | U2.7 113.73,92.27 113.5,92.5
  Top 0.6: 1HDRV.2 113.36,98.36 114,99 119,99 119,95 116,95 113.5,92.5
N$15
  Top 0.5: C17.1 R20.2 109.1,59.9 109.3,59.7 110.33,59.7 IC1.2 110.44,59.6 112.3,59.6 112.9,59 113,59 113,58 113.91,57.09 IC1.5
N$16
  Top 0.6: D11.1 118.95,44 110,44 | 110,44 109.6,44.4 2LODRV.3 | 110,44 110,44.2 109.9,43.97 2LODRV.2
  Top 1: 110,44.2 R18.2
N$17
  Top 0.5: R25.2 162.8,6.9 R26.2 166,7.1 U$2.4 U$2.3
N$18
  Top 0.5: IC1.6 117.64,58.37 118,58 120,58 R24.1 R23.2
N$23
  Top 0.5: R9.2 R27.1
N$29
  Top 0.406: 101,4.5 47.5,4.5 R12.E
  Top 0.5: 101,4.5 103.1,4.5 R10.2 102.9,5.3 R29.2 | 40,5 R28.1 40.79,4.66 R12.E
N$30
  Top 0.406: R9.1 40.17,10.24 41,9.68 R12.A
  Top 0.5: R28.2 40,10.08 40.17,10.24
N$31
  Top 0.4: 93.9,6 99,6 103,10 103,14 103.1,14 R7.2
  Top 0.406: R12.S 46.5,7.2 50,6 93.9,6
O_IFB  (via drill 0.51)  (1 unrouted)
  Top 0.254: JP7.1 152,14
  Top 0.406: R24.2 119.1,61.1 118,60 116.8,60 116.5,59.7 115.67,59.7 IC1.7
  Top 1: v120,63 R24.2 120,62 | 152,14 v152,31
PUMP+  (1 unrouted)
  Top 0.254: P+2.1 174,12 174.38,12.27
  Top 0.406: P+1.1 177,14 178,15 178,22 177.65,23.35 R11.1 173.4,24.35 TRAFO.3
  pour Top (isolate 2, rank 2): 178,25 178,12 174,12 174,16 177,16 177,23.6 173,23.6 173,25
  pour Bottom (isolate 2, rank 3): 58,24 58,8 81,8 81,14 98,14 101,16 101,103 114,103 114,113 118,113 119,112 119,109 124,109 124,112 138,112 138,108 139,107 144,107 144,112 160,112 163,109 163,107 179,107 179,121 87,121 87,111 80,111 80,118 57,118 57,102 79,102 79,107 88,107 93,112 110,112 110,110 107,107 96,107 94,105 94,21 92,19 80,19 80,24
  pour Top (isolate 2, rank 4): 58,24 58,8 81,8 81,14 98,14 100,16 100,92 101,96 101,103 113,103 114,113 118,113 119,112 119,109 124,109 124,112 138,112 138,108 139,107 144,107 144,112 160,112 163,109 163,107 167,107 167,121 87,121 87,111 80,111 80,118 57,118 57,102 79,102 79,107 88,107 93,112 110,112 110,110 107,107 96,107 94,105 94,21 92,19 80,19 80,24
RED
  Top 0.254: 104,30 C12.2 | 2HDRV.5 105,26.5
  Top 0.5: 2HDRV.4 109,26.5 108.5,27 | ROUT6.2 92,23 86,23 86,22.43 Q3.S | 2HDRV.5 105.4,27.3 | 105,26.5 105.5,26.5 106,27
  Top 0.6: U1.6 104,35 104,30 104,27.7
  Top 1: 105.4,27.3 103,28 | 106,27 108.5,27
  pour Bottom (isolate 2, rank 3): 40,63 46,63 47,62 86,62 87,45 82,45 80,43 80,36 86,30 86,21 85,20 84,20 83,21 83,27 58,27
  pour Top (isolate 2): 84,23 84,26 94,26 103,35 104,35 104,26 98,26 96,24 93,24 91,22 89,22 88,21 84,21
  pour Top (isolate 2, rank 3): 40,63 46,63 47,62 86,62 87,45 82,45 80,43 80,36 86,30 86,21 85,20 84,20 83,21 83,27 58,27
SCR2
  pour Top (isolate 2): 178,99 178,96 164,96 164,99
  pour Bottom (isolate 2): 178,99 178,96 164,96 164,99
SNUB1
  pour Top (isolate 2, rank 2): 162,99 162,87 155,87 155,99
  pour Bottom (isolate 2, rank 2): 162,99 162,87 155,87 155,99
SNUB2
  pour Top (isolate 2, rank 2): 162,83 162,71 155,71 155,83
  pour Bottom (isolate 2, rank 2): 162,83 162,71 155,71 155,83
SOURCE
  pour Top (isolate 2): 178,83 178,80 164,80 164,83
  pour Bottom (isolate 2): 178,83 178,80 164,80 164,83
TFB
  Top 0.5: NTC.1 111.73,9.73 114,12 114,12.78 JP7.16 114.22,14.22 115,15 115,16.8 C2.1
V12  (via drill 0.6)
  Top 0.254: 114,53 R21.2 | V12_2.1 165,11 165,12 165.17,12
  Top 0.406: C7.+ 171.45,16.45 170,15 167,15 V12_1.1 | V12_1.1 R13.2 | D9.K 163,17 V12_1.1
  Top 0.5: JP7.12 124.38,15.62 v124.4,15.3 124.3,15.4 | V12_2.1 168,11 169,10 169,8.75 U$2.1 | 2LODRV.8 104.4,41.6 105,41 | 2LODRV.1 108.5,41 | 1LODRV.8 104.4,67.6 105,67 | 108.5,67 108.75,67.25 1LODRV.1 | C8.+ 123.5,17.6 124.3,16.8
  Top 0.6: 109,82 D10.A | 109,82 110,81 110.46,81.46 U2.1 v111,81 | C14.1 108,81 109,82 | 1LODRV.1 109.69,68 | D8.A 119,31.5 U1.1 | v116,41 C16.1 | 110.69,41 2LODRV.1 | 115.69,61.7 IC1.8
  Top 1: v116,41 110.69,41 | v116,62.7 115.69,61.7 | v116,53 114,53 | v163,11 V12_2.1 | v117.8,27.6 117.85,27.55 C13.1 120,29.4 D8.A | 108.5,41 105,41 | 108.5,67 105,67 | 108.75,67.25 109,67 v116,67 115,68 C15.1 | 124.3,15.4 124.3,16.8
  Bottom 0.5: 124,17 124.1,17 124.3,16.8 124.3,15.4 v124.4,15.3
  Bottom 1: 116,28 116,25 124,17 | 116,28 v116,41 v116,53 v116,62.7 v116,67 116,74 v111,81 | v124.4,15.3 124.3,11 127,8 163,8 v163,11 | v117.8,27.6 116.4,27.6 116,28
  pour Top (isolate 2): 172,18 172,12 163,12 163,17 170,17
  pour Top (isolate 1.5, rank 2): 105,86 110,86 111,83 112,83 112,80 105,80
VB1
  Top 0.5: 106.4,96.6 1HDRV.8 | 111,96.5 1HDRV.1 | 112,88.27 U2.8 | C11.1 115.35,97.45 114.4,96.5
  Top 1: 106.4,96.6 107,96 109,96 | 109,96 111,96 111,96.5 | 109,96 D10.K 109.6,91.4 112,89 112,88.27
  pour Top (isolate 1.5, rank 2): 106,97 116,97 116,95 113,92 113,88 112,89 110,90 105,90 105,96
VB2
  Top 0.254: 2HDRV.8 105,22.5 | 109,22.5 2HDRV.1
  Top 0.5: 2HDRV.1 111.3,22.59 | 114,28.6 D8.K | 105,22.5 105,22 | 109,22 109,22.5 | 111.19,31.19 U1.8
  Top 1: 114,28.6 114,23 113.59,22.59 111.3,22.59 | 105,22 109,22 | 111,31 C12.1 | 111,31 111,32 112,31 113,31 114,30 114.4,30 D8.K | 111,31 111.19,31.19
VDD  (via drill 0.6)
  Top 0.5: U$2.2 168.75,4.75 168,4.5 163.9,4.5 R26.1 156.1,4.9 v156,4.5 | NTC.2 118.73,9 VENT.2 | VENT.2 120.73,9.27 122,8 123.3,8 C6.+ | JP7.14 119.3,9.57 VENT.2
  Bottom 0.5: v156,4.5 125,4.5 121.5,9 119.27,9 VENT.2
VFB
  Top 0.5: 105.1,17.1 107,19 117,19 117,17 | 117,17 117,13.24 | 117,17 C10.1
  Top 0.8: R7.1 105.1,17.1 | 117,13.24 JP7.15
